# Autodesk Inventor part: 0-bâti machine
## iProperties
Created: 2011-02
Part Number: 0-bâti machine
Document SubType Name: Modeling
Designer: eric
Density: 1 g/cm^3
Author: eric
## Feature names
1. Base1
